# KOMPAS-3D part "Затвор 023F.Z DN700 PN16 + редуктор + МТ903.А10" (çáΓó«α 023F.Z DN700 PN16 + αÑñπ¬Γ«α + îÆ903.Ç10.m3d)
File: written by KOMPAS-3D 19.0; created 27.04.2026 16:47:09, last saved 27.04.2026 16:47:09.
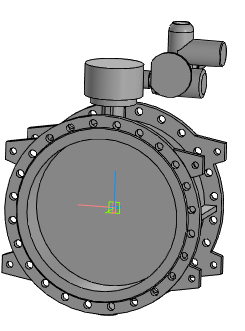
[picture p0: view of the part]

Document properties: Полное имя файла: ..\..\Затвор 023F.Z DN400-DN1600 + редуктор + МТ903\Затвор 023F.Z DN700 PN16 + редуктор + МТ903.А10.a3d

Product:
- Part/product: Затвор 023F.Z DN700 PN16 + редуктор + МТ903.А10
    Масса: 669.586

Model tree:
1. Операция без истории:1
